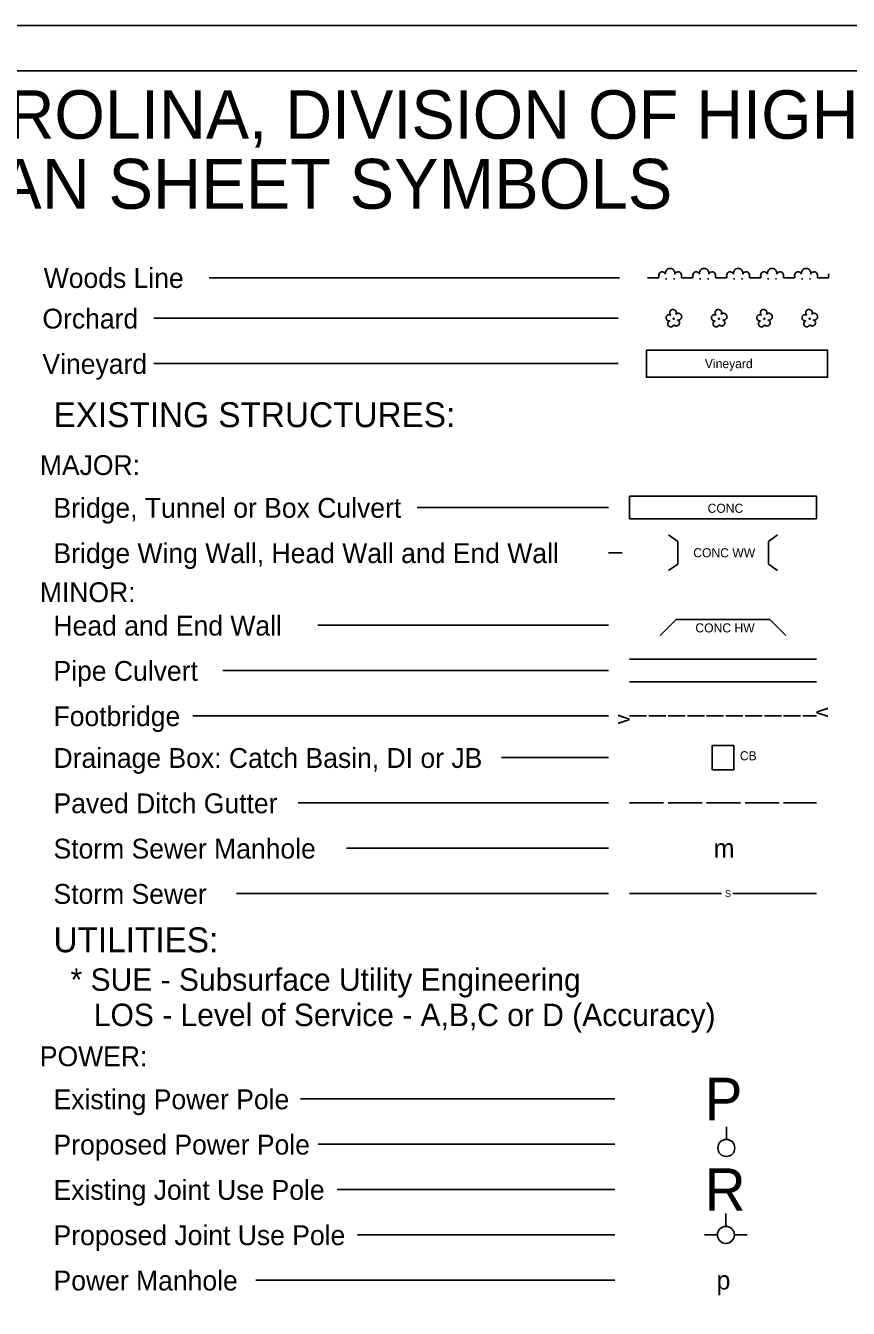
# Model space of a CAD drawing. Extents: x 2058169 to 2059852, y 675171 to 676266.
# Drawn here: x 2059089 to 2059452, y 675700 to 676266 of the extents above; entities that cross this region are included whole.
import ezdxf

# ---------------------------------------------------------------- set-up
doc = ezdxf.new("R2010")
doc.units = 0
for name, color, linetype in [('Sheet Block Title CELL', 7, 'Continuous'), ('Sheet Clip Boundary CELL', 7, 'Continuous'), ('Sheet Sticker Exception Certification CELL', 7, 'Continuous'), ('Sheet Symbology CELL', 7, 'Continuous')]:
    doc.layers.add(name, color=color, linetype=linetype)

msp = doc.modelspace()

# ---------------------------------------------------------------- linework, layer by layer
at = {"layer": 'Sheet Block Title CELL'}
msp.add_lwpolyline([(2058181.51, 675191.07), (2059847.5, 675191.08), (2059847.51, 676246.07), (2058181.51, 676246.07)], close=True, dxfattribs=at)
at = {"layer": 'Sheet Clip Boundary CELL'}
msp.add_line((2059852.01, 676266.07), (2058168.51, 676266.07), dxfattribs=at)
at = {"layer": 'Sheet Sticker Exception Certification CELL'}
msp.add_lwpolyline([(2058168.51, 675171.07), (2059852.01, 675171.07), (2059852.01, 676266.07), (2058168.51, 676266.07)], close=True, dxfattribs=at)
at = {"layer": 'Sheet Symbology CELL'}
for p, q in [((2059351.11, 676154.81), (2059169.98, 676154.81)), ((2059363.5, 676154.81), (2059368.5, 676154.81)), ((2059378.5, 676154.81), (2059383.5, 676154.81)), ((2059393.5, 676154.81), (2059398.5, 676154.81)), ((2059408.5, 676154.81), (2059413.5, 676154.81)), ((2059423.5, 676154.81), (2059428.5, 676154.81)), ((2059438.5, 676154.81), (2059443.5, 676154.81)), ((2059371.45, 676154.31), (2059371.95, 676154.31)), ((2059374.95, 676154.31), (2059375.45, 676154.31)), ((2059386.45, 676154.31), (2059386.95, 676154.31)), ((2059389.95, 676154.31), (2059390.45, 676154.31)), ((2059401.45, 676154.31), (2059401.95, 676154.31)), ((2059404.95, 676154.31), (2059405.45, 676154.31)), ((2059416.45, 676154.31), (2059416.95, 676154.31)), ((2059419.95, 676154.31), (2059420.45, 676154.31)), ((2059431.45, 676154.31), (2059431.95, 676154.31)), ((2059434.95, 676154.31), (2059435.45, 676154.31)), ((2059350.54, 676136.88), (2059145.6, 676136.88)), ((2059350.54, 676116.88), (2059145.6, 676116.88)), ((2059346.23, 676053.38), (2059261.8, 676053.38)), ((2059372.68, 676041.24), (2059376.78, 676038.38)), ((2059420.88, 676041.24), (2059416.78, 676038.38)), ((2059376.78, 676038.38), (2059376.78, 676028.38)), ((2059416.78, 676038.38), (2059416.78, 676028.38)), ((2059346.23, 676033.38), (2059352.21, 676033.38)), ((2059372.68, 676025.52), (2059376.78, 676028.38)), ((2059420.88, 676025.52), (2059416.78, 676028.38)), ((2059369.08, 675996.81), (2059376.15, 676003.88)), ((2059376.15, 676003.88), (2059417.4, 676003.88)), ((2059417.4, 676003.88), (2059424.48, 675996.81)), ((2059346.23, 676001.38), (2059217.93, 676001.38)), ((2059355.53, 675986.38), (2059438.03, 675986.38)), ((2059346.23, 675981.38), (2059176.04, 675981.38)), ((2059355.53, 675976.38), (2059438.03, 675976.38)), ((2059346.23, 675961.38), (2059162.75, 675961.38)), ((2059355.53, 675961.38), (2059363.03, 675961.38)), ((2059364.03, 675961.38), (2059371.53, 675961.38)), ((2059372.53, 675961.38), (2059380.03, 675961.38)), ((2059381.03, 675961.38), (2059388.53, 675961.38)), ((2059389.53, 675961.38), (2059397.03, 675961.38)), ((2059398.03, 675961.38), (2059405.53, 675961.38)), ((2059406.53, 675961.38), (2059414.03, 675961.38)), ((2059415.03, 675961.38), (2059422.53, 675961.38)), ((2059423.53, 675961.38), (2059431.03, 675961.38)), ((2059432.03, 675961.38), (2059438.03, 675961.38)), ((2059346.23, 675942.95), (2059299.03, 675942.95)), ((2059346.23, 675922.95), (2059209.28, 675922.95)), ((2059355.53, 675922.95), (2059370.53, 675922.95)), ((2059372.53, 675922.95), (2059387.53, 675922.95)), ((2059389.53, 675922.95), (2059404.53, 675922.95)), ((2059406.53, 675922.95), (2059421.53, 675922.95)), ((2059423.53, 675922.95), (2059438.03, 675922.95)), ((2059346.23, 675902.95), (2059230.55, 675902.95)), ((2059346.23, 675882.95), (2059182.03, 675882.95)), ((2059355.53, 675882.95), (2059396.05, 675882.95)), ((2059401.05, 675882.95), (2059438.03, 675882.95)), ((2059349.01, 675792.27), (2059210.31, 675792.27)), ((2059398.24, 675774.38), (2059398.24, 675780)), ((2059349.01, 675772.27), (2059218.1, 675772.27)), ((2059349.01, 675752.27), (2059226.5, 675752.27)), ((2059398.03, 675736.03), (2059398.03, 675741.65)), ((2059349.01, 675732.27), (2059235.5, 675732.27)), ((2059394.28, 675732.28), (2059388.65, 675732.28)), ((2059401.78, 675732.28), (2059407.4, 675732.28)), ((2059349.01, 675712.27), (2059190.51, 675712.27))]:
    msp.add_line(p, q, dxfattribs=at)
for points in [[(2059375.98, 676138.63), (2059376.13, 676138.93), (2059376.18, 676139.23), (2059376.13, 676139.53), (2059376.08, 676139.83), (2059375.93, 676140.08), (2059375.78, 676140.33), (2059375.53, 676140.53), (2059375.28, 676140.68), (2059374.93, 676140.78), (2059374.68, 676140.78), (2059374.38, 676140.73), (2059374.08, 676140.63), (2059373.83, 676140.48), (2059373.58, 676140.28), (2059373.43, 676139.98), (2059373.33, 676139.73), (2059373.28, 676139.43), (2059373.28, 676139.13), (2059373.33, 676138.83), (2059373.48, 676138.58), (2059373.68, 676138.28), (2059373.43, 676138.43), (2059373.13, 676138.48), (2059372.83, 676138.48), (2059372.58, 676138.38), (2059372.33, 676138.28), (2059372.08, 676138.08), (2059371.88, 676137.88), (2059371.73, 676137.63), (2059371.68, 676137.38), (2059371.63, 676137.03), (2059371.68, 676136.78), (2059371.78, 676136.53), (2059371.98, 676136.28), (2059372.13, 676136.08), (2059372.38, 676135.93), (2059372.68, 676135.78), (2059372.93, 676135.73), (2059373.23, 676135.73), (2059372.98, 676135.63), (2059372.73, 676135.43), (2059372.58, 676135.23), (2059372.48, 676134.93), (2059372.38, 676134.63), (2059372.38, 676134.38), (2059372.43, 676134.08), (2059372.58, 676133.83), (2059372.73, 676133.58), (2059372.93, 676133.38), (2059373.18, 676133.23), (2059373.43, 676133.13), (2059373.73, 676133.13), (2059374.03, 676133.13), (2059374.28, 676133.18), (2059374.53, 676133.38), (2059374.78, 676133.53), (2059375.03, 676133.98)], [(2059375.03, 676133.98), (2059375.63, 676133.63), (2059375.93, 676133.53), (2059376.23, 676133.48), (2059376.53, 676133.53), (2059376.78, 676133.63), (2059377.03, 676133.78), (2059377.28, 676133.98), (2059377.43, 676134.23), (2059377.53, 676134.48), (2059377.63, 676134.78), (2059377.58, 676135.08), (2059377.53, 676135.38), (2059377.33, 676135.68), (2059377.18, 676135.88), (2059376.93, 676136.03), (2059376.63, 676136.18), (2059376.93, 676136.13), (2059377.28, 676136.13), (2059377.53, 676136.23), (2059377.83, 676136.38), (2059378.08, 676136.53), (2059378.28, 676136.78), (2059378.43, 676137.08), (2059378.48, 676137.38), (2059378.53, 676137.68), (2059378.48, 676137.98), (2059378.38, 676138.28), (2059378.18, 676138.53), (2059377.93, 676138.78), (2059377.68, 676138.93), (2059377.38, 676139.03), (2059377.08, 676139.08), (2059376.78, 676139.08), (2059376.48, 676138.98), (2059376.23, 676138.83), (2059375.98, 676138.63)], [(2059395.98, 676138.63), (2059396.13, 676138.93), (2059396.18, 676139.23), (2059396.13, 676139.53), (2059396.08, 676139.83), (2059395.93, 676140.08), (2059395.78, 676140.33), (2059395.53, 676140.53), (2059395.28, 676140.68), (2059394.93, 676140.78), (2059394.68, 676140.78), (2059394.38, 676140.73), (2059394.08, 676140.63), (2059393.83, 676140.48), (2059393.58, 676140.28), (2059393.43, 676139.98), (2059393.33, 676139.73), (2059393.28, 676139.43), (2059393.28, 676139.13), (2059393.33, 676138.83), (2059393.48, 676138.58), (2059393.68, 676138.28), (2059393.43, 676138.43), (2059393.13, 676138.48), (2059392.83, 676138.48), (2059392.58, 676138.38), (2059392.33, 676138.28), (2059392.08, 676138.08), (2059391.88, 676137.88), (2059391.73, 676137.63), (2059391.68, 676137.38), (2059391.63, 676137.03), (2059391.68, 676136.78), (2059391.78, 676136.53), (2059391.98, 676136.28), (2059392.13, 676136.08), (2059392.38, 676135.93), (2059392.68, 676135.78), (2059392.93, 676135.73), (2059393.23, 676135.73), (2059392.98, 676135.63), (2059392.73, 676135.43), (2059392.58, 676135.23), (2059392.48, 676134.93), (2059392.38, 676134.63), (2059392.38, 676134.38), (2059392.43, 676134.08), (2059392.58, 676133.83), (2059392.73, 676133.58), (2059392.93, 676133.38), (2059393.18, 676133.23), (2059393.43, 676133.13), (2059393.73, 676133.13), (2059394.03, 676133.13), (2059394.28, 676133.18), (2059394.53, 676133.38), (2059394.78, 676133.53), (2059395.03, 676133.98)], [(2059395.03, 676133.98), (2059395.63, 676133.63), (2059395.93, 676133.53), (2059396.23, 676133.48), (2059396.53, 676133.53), (2059396.78, 676133.63), (2059397.03, 676133.78), (2059397.28, 676133.98), (2059397.43, 676134.23), (2059397.53, 676134.48), (2059397.63, 676134.78), (2059397.58, 676135.08), (2059397.53, 676135.38), (2059397.33, 676135.68), (2059397.18, 676135.88), (2059396.93, 676136.03), (2059396.63, 676136.18), (2059396.93, 676136.13), (2059397.28, 676136.13), (2059397.53, 676136.23), (2059397.83, 676136.38), (2059398.08, 676136.53), (2059398.28, 676136.78), (2059398.43, 676137.08), (2059398.48, 676137.38), (2059398.53, 676137.68), (2059398.48, 676137.98), (2059398.38, 676138.28), (2059398.18, 676138.53), (2059397.93, 676138.78), (2059397.68, 676138.93), (2059397.38, 676139.03), (2059397.08, 676139.08), (2059396.78, 676139.08), (2059396.48, 676138.98), (2059396.23, 676138.83), (2059395.98, 676138.63)], [(2059415.98, 676138.63), (2059416.13, 676138.93), (2059416.18, 676139.23), (2059416.13, 676139.53), (2059416.08, 676139.83), (2059415.93, 676140.08), (2059415.78, 676140.33), (2059415.53, 676140.53), (2059415.28, 676140.68), (2059414.93, 676140.78), (2059414.68, 676140.78), (2059414.38, 676140.73), (2059414.08, 676140.63), (2059413.83, 676140.48), (2059413.58, 676140.28), (2059413.43, 676139.98), (2059413.33, 676139.73), (2059413.28, 676139.43), (2059413.28, 676139.13), (2059413.33, 676138.83), (2059413.48, 676138.58), (2059413.68, 676138.28), (2059413.43, 676138.43), (2059413.13, 676138.48), (2059412.83, 676138.48), (2059412.58, 676138.38), (2059412.33, 676138.28), (2059412.08, 676138.08), (2059411.88, 676137.88), (2059411.73, 676137.63), (2059411.68, 676137.38), (2059411.63, 676137.03), (2059411.68, 676136.78), (2059411.78, 676136.53), (2059411.98, 676136.28), (2059412.13, 676136.08), (2059412.38, 676135.93), (2059412.68, 676135.78), (2059412.93, 676135.73), (2059413.23, 676135.73), (2059412.98, 676135.63), (2059412.73, 676135.43), (2059412.58, 676135.23), (2059412.48, 676134.93), (2059412.38, 676134.63), (2059412.38, 676134.38), (2059412.43, 676134.08), (2059412.58, 676133.83), (2059412.73, 676133.58), (2059412.93, 676133.38), (2059413.18, 676133.23), (2059413.43, 676133.13), (2059413.73, 676133.13), (2059414.03, 676133.13), (2059414.28, 676133.18), (2059414.53, 676133.38), (2059414.78, 676133.53), (2059415.03, 676133.98)], [(2059415.03, 676133.98), (2059415.63, 676133.63), (2059415.93, 676133.53), (2059416.23, 676133.48), (2059416.53, 676133.53), (2059416.78, 676133.63), (2059417.03, 676133.78), (2059417.28, 676133.98), (2059417.43, 676134.23), (2059417.53, 676134.48), (2059417.63, 676134.78), (2059417.58, 676135.08), (2059417.53, 676135.38), (2059417.33, 676135.68), (2059417.18, 676135.88), (2059416.93, 676136.03), (2059416.63, 676136.18), (2059416.93, 676136.13), (2059417.28, 676136.13), (2059417.53, 676136.23), (2059417.83, 676136.38), (2059418.08, 676136.53), (2059418.28, 676136.78), (2059418.43, 676137.08), (2059418.48, 676137.38), (2059418.53, 676137.68), (2059418.48, 676137.98), (2059418.38, 676138.28), (2059418.18, 676138.53), (2059417.93, 676138.78), (2059417.68, 676138.93), (2059417.38, 676139.03), (2059417.08, 676139.08), (2059416.78, 676139.08), (2059416.48, 676138.98), (2059416.23, 676138.83), (2059415.98, 676138.63)], [(2059435.98, 676138.63), (2059436.13, 676138.93), (2059436.18, 676139.23), (2059436.13, 676139.53), (2059436.08, 676139.83), (2059435.93, 676140.08), (2059435.78, 676140.33), (2059435.53, 676140.53), (2059435.28, 676140.68), (2059434.93, 676140.78), (2059434.68, 676140.78), (2059434.38, 676140.73), (2059434.08, 676140.63), (2059433.83, 676140.48), (2059433.58, 676140.28), (2059433.43, 676139.98), (2059433.33, 676139.73), (2059433.28, 676139.43), (2059433.28, 676139.13), (2059433.33, 676138.83), (2059433.48, 676138.58), (2059433.68, 676138.28), (2059433.43, 676138.43), (2059433.13, 676138.48), (2059432.83, 676138.48), (2059432.58, 676138.38), (2059432.33, 676138.28), (2059432.08, 676138.08), (2059431.88, 676137.88), (2059431.73, 676137.63), (2059431.68, 676137.38), (2059431.63, 676137.03), (2059431.68, 676136.78), (2059431.78, 676136.53), (2059431.98, 676136.28), (2059432.13, 676136.08), (2059432.38, 676135.93), (2059432.68, 676135.78), (2059432.93, 676135.73), (2059433.23, 676135.73), (2059432.98, 676135.63), (2059432.73, 676135.43), (2059432.58, 676135.23), (2059432.48, 676134.93), (2059432.38, 676134.63), (2059432.38, 676134.38), (2059432.43, 676134.08), (2059432.58, 676133.83), (2059432.73, 676133.58), (2059432.93, 676133.38), (2059433.18, 676133.23), (2059433.43, 676133.13), (2059433.73, 676133.13), (2059434.03, 676133.13), (2059434.28, 676133.18), (2059434.53, 676133.38), (2059434.78, 676133.53), (2059435.03, 676133.98)], [(2059435.03, 676133.98), (2059435.63, 676133.63), (2059435.93, 676133.53), (2059436.23, 676133.48), (2059436.53, 676133.53), (2059436.78, 676133.63), (2059437.03, 676133.78), (2059437.28, 676133.98), (2059437.43, 676134.23), (2059437.53, 676134.48), (2059437.63, 676134.78), (2059437.58, 676135.08), (2059437.53, 676135.38), (2059437.33, 676135.68), (2059437.18, 676135.88), (2059436.93, 676136.03), (2059436.63, 676136.18), (2059436.93, 676136.13), (2059437.28, 676136.13), (2059437.53, 676136.23), (2059437.83, 676136.38), (2059438.08, 676136.53), (2059438.28, 676136.78), (2059438.43, 676137.08), (2059438.48, 676137.38), (2059438.53, 676137.68), (2059438.48, 676137.98), (2059438.38, 676138.28), (2059438.18, 676138.53), (2059437.93, 676138.78), (2059437.68, 676138.93), (2059437.38, 676139.03), (2059437.08, 676139.08), (2059436.78, 676139.08), (2059436.48, 676138.98), (2059436.23, 676138.83), (2059435.98, 676138.63)], [(2059375.13, 676136.88), (2059374.98, 676136.88), (2059374.88, 676136.83), (2059374.78, 676136.78), (2059374.78, 676136.63), (2059374.78, 676136.53), (2059374.88, 676136.43), (2059375.03, 676136.43), (2059375.13, 676136.43), (2059375.23, 676136.53), (2059375.28, 676136.68), (2059375.23, 676136.78), (2059375.13, 676136.88)], [(2059395.13, 676136.88), (2059394.98, 676136.88), (2059394.88, 676136.83), (2059394.78, 676136.78), (2059394.78, 676136.63), (2059394.78, 676136.53), (2059394.88, 676136.43), (2059395.03, 676136.43), (2059395.13, 676136.43), (2059395.23, 676136.53), (2059395.28, 676136.68), (2059395.23, 676136.78), (2059395.13, 676136.88)], [(2059415.13, 676136.88), (2059414.98, 676136.88), (2059414.88, 676136.83), (2059414.78, 676136.78), (2059414.78, 676136.63), (2059414.78, 676136.53), (2059414.88, 676136.43), (2059415.03, 676136.43), (2059415.13, 676136.43), (2059415.23, 676136.53), (2059415.28, 676136.68), (2059415.23, 676136.78), (2059415.13, 676136.88)], [(2059435.13, 676136.88), (2059434.98, 676136.88), (2059434.88, 676136.83), (2059434.78, 676136.78), (2059434.78, 676136.63), (2059434.78, 676136.53), (2059434.88, 676136.43), (2059435.03, 676136.43), (2059435.13, 676136.43), (2059435.23, 676136.53), (2059435.28, 676136.68), (2059435.23, 676136.78), (2059435.13, 676136.88)], [(2059362.93, 676122.88), (2059442.93, 676122.88), (2059442.93, 676110.88), (2059362.93, 676110.88), (2059362.93, 676122.88)], [(2059355.53, 676058.38), (2059438.03, 676058.38), (2059438.03, 676048.38), (2059355.53, 676048.38), (2059355.53, 676058.38)]]:
    msp.add_lwpolyline(points, dxfattribs=at)
msp.add_lwpolyline([(2059391.96, 675937.63), (2059401.58, 675937.63), (2059401.58, 675948.27), (2059391.96, 675948.27)], close=True, dxfattribs=at)
for centre in [(2059398.24, 675770.63), (2059398.03, 675732.27)]:
    msp.add_circle(centre, 3.75, dxfattribs=at)
for centre, radius, start, end in [((2059369.95, 676155.83), 1.58, 18.4349, 219.2315), ((2059373.45, 676156.83), 2.06, 345.9638, 194.0362), ((2059376.95, 676155.83), 1.58, 320.7685, 161.565), ((2059384.95, 676155.83), 1.58, 18.4349, 219.2315), ((2059388.45, 676156.83), 2.06, 345.9638, 194.0362), ((2059391.95, 676155.83), 1.58, 320.7685, 161.565), ((2059399.95, 676155.83), 1.58, 18.4349, 219.2315), ((2059403.45, 676156.83), 2.06, 345.9638, 194.0362), ((2059406.95, 676155.83), 1.58, 320.7685, 161.565), ((2059414.95, 676155.83), 1.58, 18.4349, 219.2315), ((2059418.45, 676156.83), 2.06, 345.9638, 194.0362), ((2059421.95, 676155.83), 1.58, 320.7685, 161.565), ((2059429.95, 676155.83), 1.58, 18.4349, 219.2315), ((2059433.45, 676156.83), 2.06, 345.9638, 194.0362), ((2059436.95, 676155.83), 1.58, 320.7685, 161.565), ((2059444.95, 676155.83), 1.58, 156.251, 203.749)]:
    msp.add_arc(centre, radius, start, end, dxfattribs=at)

# ---------------------------------------------------------------- texts
for s, height, rotation, p in [('STATE OF NORTH CAROLINA, DIVISION OF HIGHWAYS', 21.419, 360, (2058783.41, 676216.12)), ('CONVENTIONAL  PLAN SHEET SYMBOLS', 22.0323, 360, (2058791.54, 676185.24)), ('Woods Line', 8.75, 360, (2059096.95, 676150.29)), ('Orchard', 8.75, 360, (2059096.38, 676132.36)), ('Vineyard', 8.75, 360, (2059096.38, 676112.36)), ('Vineyard', 4, 0, (2059388.76, 676114.88)), ('EXISTING STRUCTURES:', 11, 360, (2059101.26, 676088.83)), ('MAJOR:', 8.75, 360, (2059095.24, 676067.71)), ('Bridge, Tunnel or Box Culvert', 8.75, 360, (2059101.26, 676048.83)), ('CONC', 4, 360, (2059389.96, 676051.02)), ('Bridge Wing Wall, Head Wall and End Wall', 8.75, 360, (2059101.26, 676028.83)), ('CONC WW', 4, 0, (2059383.65, 676031.38)), ('MINOR:', 8.75, 360, (2059095.24, 676011.59)), ('Head and End Wall', 8.75, 360, (2059101.26, 675996.83)), ('CONC HW', 4, 360, (2059384.58, 675998.22)), ('Pipe Culvert', 8.75, 360, (2059101.26, 675976.85)), ('Footbridge', 8.75, 360, (2059101.28, 675956.85)), ('v', 6.6, 89.7591, (2059355.51, 675957.65)), ('v', 6.6, 270.2409, (2059438.01, 675965.12)), ('Drainage Box: Catch Basin, DI or JB', 8.75, 360, (2059101.28, 675938.41)), ('CB', 4, 360, (2059404.21, 675941.77)), ('Paved Ditch Gutter', 8.75, 360, (2059101.28, 675918.4)), ('Storm Sewer Manhole', 8.75, 360, (2059101.28, 675898.4)), ('m', 8.25, 360, (2059392.65, 675898.82)), ('Storm Sewer', 8.75, 360, (2059101.28, 675878.4)), ('S', 3, 360, (2059397.65, 675881.45)), ('UTILITIES:', 11, 360, (2059101.26, 675857.03)), ('* SUE - Subsurface Utility Engineering', 9.9, 360, (2059108.8, 675840.01)), ('LOS - Level of Service - A,B,C or D (Accuracy) ', 9.9, 360, (2059119.07, 675824.44)), ('POWER:', 8.75, 360, (2059095.24, 675806.73)), ('P', 18.75, 360, (2059388.65, 675782.89)), ('Existing Power Pole', 8.75, 360, (2059101.28, 675787.73)), ('Proposed Power Pole', 8.75, 360, (2059101.28, 675767.73)), ('R', 18.75, 360, (2059388.65, 675742.89)), ('Existing Joint Use Pole', 8.75, 360, (2059101.28, 675747.74)), ('Proposed Joint Use Pole', 8.75, 360, (2059101.29, 675727.73)), ('Power Manhole', 8.75, 360, (2059101.29, 675707.73)), ('p', 8.25, 360, (2059393.9, 675708.14))]:
    msp.add_text(s, height=height, rotation=rotation, dxfattribs=at).set_placement(p)

doc.saveas('drawing.dxf')
